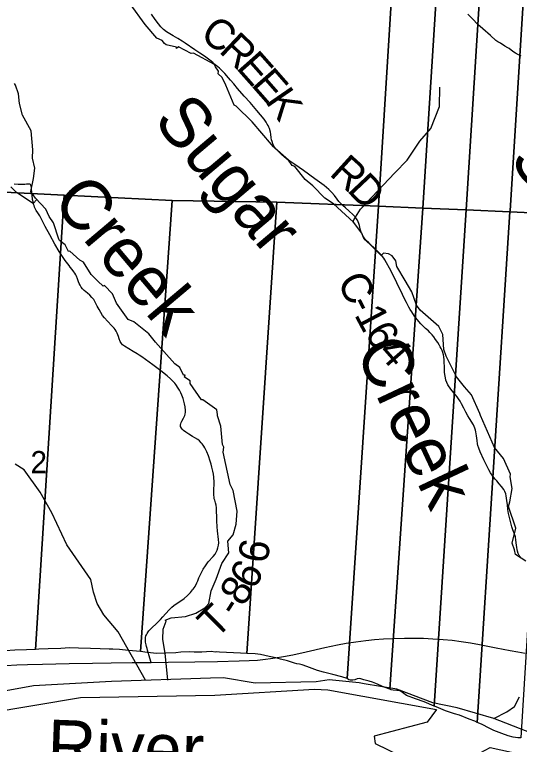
# Model space of a CAD drawing. Extents: x 0 to 34, y 0 to 22.
# Drawn here: x 28.533 to 29.485, y 15.294 to 16.671 of the extents above; entities that cross this region are included whole.
import ezdxf

# ---------------------------------------------------------------- set-up
doc = ezdxf.new("R2010")
doc.units = 0
for name, color, linetype in [('GM_X_County_Road', 7, 'Continuous'), ('GM_X_County_Road_Text', 7, 'Continuous'), ('GM_X_County_Text', 7, 'Continuous'), ('GM_X_Major_River', 7, 'Continuous'), ('GM_X_Major_River_Text', 7, 'Continuous'), ('GM_X_Minor_River', 7, 'Continuous'), ('GM_X_Minor_River_Text', 7, 'Continuous'), ('GM_X_Section', 7, 'Continuous'), ('GM_X_Section_Text', 7, 'Continuous'), ('GM_X_State_Route', 7, 'Continuous'), ('GM_X_Township_Road', 7, 'Continuous'), ('GM_X_Township_Road_Text', 7, 'Continuous'), ('SH_Cut_Line', 7, 'Continuous')]:
    doc.layers.add(name, color=color, linetype=linetype)

msp = doc.modelspace()

# ---------------------------------------------------------------- linework, layer by layer
at = {"layer": 'GM_X_County_Road'}
for points in [[(29.4879, 15.6455), (29.4848, 15.6503), (29.4829, 15.6542), (29.4816, 15.6581), (29.4808, 15.6614), (29.4803, 15.6655), (29.4799, 15.6698), (29.4788, 15.679), (29.4778, 15.6852), (29.4755, 15.6921), (29.473, 15.6984), (29.4711, 15.7043), (29.4678, 15.7168), (29.465, 15.7294), (29.4637, 15.737), (29.4625, 15.7459), (29.4616, 15.7542), (29.4605, 15.7627), (29.4596, 15.7668), (29.4577, 15.7711), (29.4556, 15.7746), (29.4516, 15.7801), (29.4468, 15.7857), (29.4424, 15.7908), (29.4393, 15.7944), (29.4349, 15.8), (29.431, 15.806), (29.4277, 15.8118), (29.4183, 15.8305), (29.411, 15.8461), (29.4085, 15.8527), (29.4069, 15.8576), (29.4064, 15.8611), (29.4053, 15.8675), (29.4042, 15.876), (29.4038, 15.88), (29.4032, 15.8837), (29.4025, 15.8866), (29.4011, 15.8907), (29.3984, 15.8968), (29.3911, 15.9086), (29.3878, 15.9139), (29.3844, 15.9205), (29.3803, 15.9284), (29.3763, 15.9361), (29.3732, 15.9415), (29.3703, 15.9458), (29.3675, 15.9499), (29.3618, 15.9572), (29.3559, 15.9643), (29.3503, 15.9724), (29.3481, 15.9768), (29.3463, 15.9813), (29.3455, 15.9852), (29.3449, 15.9884), (29.344, 15.9956), (29.3436, 16.0053), (29.3432, 16.0157), (29.343, 16.0196), (29.3425, 16.0248), (29.342, 16.0287), (29.3407, 16.0334), (29.3392, 16.0371), (29.3374, 16.0407), (29.3358, 16.0441), (29.3338, 16.0479), (29.3311, 16.0521), (29.3271, 16.0579), (29.3235, 16.0628), (29.3204, 16.0665), (29.3164, 16.0708), (29.3135, 16.074), (29.3083, 16.0789), (29.3045, 16.0825), (29.2995, 16.0874), (29.2924, 16.0953), (29.2873, 16.102), (29.2823, 16.1098), (29.2794, 16.1146), (29.2769, 16.1188), (29.2723, 16.1276), (29.2687, 16.1344), (29.2648, 16.1429), (29.2538, 16.1648), (29.2445, 16.1841), (29.2402, 16.1923), (29.2346, 16.2026), (29.2316, 16.2082), (29.2293, 16.2115), (29.2249, 16.217), (29.215, 16.2269), (29.2009, 16.2402), (29.1961, 16.2449), (29.1923, 16.2497), (29.1898, 16.2537), (29.1883, 16.2569), (29.1869, 16.2603), (29.1856, 16.2643), (29.1844, 16.2696), (29.1835, 16.2732), (29.1821, 16.2771), (29.1811, 16.2802), (29.1797, 16.2828), (29.1773, 16.2865), (29.1752, 16.2891), (29.1717, 16.2931), (29.1636, 16.3005), (29.157, 16.3064), (29.1521, 16.311), (29.1481, 16.3147), (29.1445, 16.3186), (29.1414, 16.3225), (29.1362, 16.3295), (29.1312, 16.3354), (29.1255, 16.341), (29.1165, 16.3486), (29.0991, 16.3611), (29.0775, 16.377), (29.0695, 16.3828), (29.0617, 16.3882), (29.0519, 16.3945), (29.046, 16.3991), (29.0363, 16.4071), (29.0293, 16.4137), (29.0252, 16.4181), (29.0219, 16.4228), (29.0198, 16.4269), (29.0184, 16.4314), (29.0176, 16.4348), (29.017, 16.4386), (29.0162, 16.4455), (29.0154, 16.4492), (29.0136, 16.4558), (29.0124, 16.4589), (29.0111, 16.4619), (29.0095, 16.4646), (29.0074, 16.468), (29.0033, 16.474), (28.9899, 16.4901), (28.9771, 16.5049), (28.9659, 16.5173), (28.9533, 16.5316), (28.9462, 16.5403), (28.9401, 16.5474), (28.9365, 16.5516), (28.9292, 16.5599), (28.9228, 16.5661), (28.9191, 16.5697), (28.913, 16.5753), (28.9069, 16.5805), (28.901, 16.5854), (28.8907, 16.5924), (28.8822, 16.5982), (28.8728, 16.6045), (28.8547, 16.6174), (28.8491, 16.6212), (28.8405, 16.6263), (28.832, 16.6312), (28.8253, 16.6351), (28.8193, 16.6388), (28.8137, 16.6429), (28.8085, 16.6479), (28.804, 16.6534), (28.7977, 16.6619), (28.791, 16.6722)], [(29.4888, 16.5932), (29.4837, 16.5953), (29.4782, 16.5983), (29.4745, 16.6005), (29.4699, 16.6042), (29.466, 16.607), (29.4636, 16.6084), (29.4577, 16.6117), (29.4493, 16.617), (29.4448, 16.6197), (29.4408, 16.6225), (29.4309, 16.6314), (29.416, 16.6442), (29.4111, 16.6488), (29.4071, 16.6525), (29.3968, 16.6634), (29.3881, 16.6719)]]:
    msp.add_lwpolyline(points, dxfattribs=at)
at = {"layer": 'GM_X_County_Text'}
msp.add_lwpolyline([(28.4427, 17.7695), (28.4159, 17.3358), (28.3944, 17.0528), (28.3527, 16.4269), (28.2867, 15.4004), (28.2799, 15.2948), (28.3301, 15.293), (28.3692, 15.2637), (28.4182, 15.3245), (28.4801, 15.3522), (28.6571, 15.3822), (28.9104, 15.3867), (29.0987, 15.3975), (29.1238, 15.3963), (29.3286, 15.3596), (29.3112, 15.3354), (29.211, 15.3094), (29.213, 15.295), (29.3097, 15.2479), (29.423, 15.2518), (29.4264, 15.2648), (29.4018, 15.2725), (29.4304, 15.2876), (29.5713, 15.2568)], dxfattribs=at)
at = {"layer": 'GM_X_Major_River'}
for points in [[(29.1018, 15.4118), (28.9867, 15.4094), (28.927, 15.4195), (28.9024, 15.4184), (28.7152, 15.4124), (28.568, 15.4039), (28.5098, 15.3936), (28.3722, 15.373)], [(29.5453, 15.3005), (29.4369, 15.3424), (29.3679, 15.3624), (29.3216, 15.3722), (29.2538, 15.3976), (29.1924, 15.4081), (29.1829, 15.4096), (29.1264, 15.4156), (29.1018, 15.4118)]]:
    msp.add_lwpolyline(points, dxfattribs=at)
at = {"layer": 'GM_X_Minor_River'}
for points in [[(29.4972, 15.6396), (29.4779, 15.6521), (29.476, 15.6605), (29.4719, 15.6734), (29.4783, 15.7019), (29.4646, 15.7429), (29.4669, 15.7516), (29.4714, 15.7764), (29.4676, 15.7988), (29.4687, 15.8037), (29.4555, 15.833), (29.4381, 15.8538), (29.4116, 15.9142), (29.4108, 15.9184), (29.3949, 15.9537), (29.3816, 15.9685), (29.3665, 15.9874), (29.3468, 16.0261), (29.3426, 16.0387), (29.3407, 16.0672), (29.3335, 16.0824), (29.298, 16.1131), (29.2912, 16.1225), (29.2824, 16.148), (29.2696, 16.1689), (29.254, 16.1954), (29.2521, 16.2064), (29.2449, 16.2159), (29.2385, 16.2193), (29.2287, 16.2205), (29.2242, 16.2166), (29.2033, 16.2375), (29.1924, 16.2474), (29.1878, 16.2584), (29.1723, 16.2796), (29.1345, 16.3137), (29.1178, 16.3243), (29.0955, 16.3478), (29.0811, 16.3596), (29.0615, 16.3843), (29.0565, 16.3861), (29.0494, 16.3964), (29.0187, 16.4237), (29.0172, 16.4256), (28.9812, 16.4688), (28.9506, 16.4984), (28.9468, 16.4999), (28.9313, 16.5379), (28.9245, 16.5523), (28.9169, 16.5595), (28.9173, 16.5644), (28.912, 16.5724), (28.9097, 16.577), (28.87, 16.5985), (28.8658, 16.5974), (28.842, 16.6103), (28.8382, 16.6072), (28.8382, 16.6095), (28.8186, 16.614), (28.8155, 16.6163), (28.811, 16.622), (28.8008, 16.6269), (28.7788, 16.6523), (28.7504, 16.6914)], [(28.8218, 15.4148), (28.8169, 15.4659), (28.8124, 15.4917), (28.8127, 15.5111), (28.8184, 15.5263), (28.8169, 15.5282), (28.8282, 15.5324), (28.8551, 15.5352), (28.8747, 15.5413), (28.8913, 15.5512), (28.8932, 15.5535), (28.8989, 15.5592), (28.9034, 15.5835), (28.9132, 15.6052), (28.9238, 15.6349), (28.937, 15.6551), (28.9351, 15.6771), (28.9453, 15.6889), (28.9509, 15.709), (28.9528, 15.7338), (28.9452, 15.7725), (28.9391, 15.7843), (28.9262, 15.8454), (28.9277, 15.8549), (28.9247, 15.8599), (28.922, 15.8941), (28.9156, 15.9138), (28.9156, 15.9165), (28.9141, 15.9248), (28.888, 15.9442), (28.8853, 15.9441), (28.8641, 15.9749), (28.8641, 15.9798), (28.8535, 15.987), (28.8543, 15.9908), (28.8513, 15.9904), (28.8444, 16.0052), (28.835, 16.0121), (28.7983, 16.0526), (28.7858, 16.0686), (28.7608, 16.0887), (28.7574, 16.0913), (28.7472, 16.0958), (28.7249, 16.1266), (28.7173, 16.144), (28.7025, 16.1596), (28.6995, 16.1584), (28.6897, 16.1679), (28.6772, 16.1804), (28.6624, 16.204), (28.6556, 16.2074), (28.6367, 16.2244), (28.6341, 16.224), (28.628, 16.2366), (28.6174, 16.2445), (28.6159, 16.2472), (28.606, 16.2779), (28.5981, 16.2901), (28.5913, 16.3041), (28.5723, 16.3246), (28.5633, 16.3375), (28.5682, 16.3618), (28.5708, 16.3812), (28.5666, 16.3998), (28.567, 16.4158), (28.5639, 16.4519), (28.5476, 16.4815), (28.5416, 16.5032), (28.54, 16.5218), (28.534, 16.5377), (28.5325, 16.5408)], [(29.1716, 16.2796), (29.1729, 16.2836), (29.1856, 16.3037), (29.2504, 16.3722), (29.2734, 16.3962), (29.2976, 16.4319), (29.3179, 16.4559), (29.3343, 16.4979), (29.3354, 16.5339)], [(28.5745, 16.3223), (28.5678, 16.3147), (28.536, 16.3355), (28.5255, 16.3458)], [(28.7794, 15.4148), (28.7281, 15.5058), (28.7011, 15.5384), (28.6882, 15.5593), (28.6817, 15.5806), (28.6763, 15.6049), (28.631, 15.6705), (28.6028, 15.7309), (28.5807, 15.7696), (28.5507, 15.8117), (28.5339, 15.8227)], [(29.4369, 15.3424), (29.4616, 15.3553), (29.4759, 15.3652), (29.4857, 15.3831)]]:
    msp.add_lwpolyline(points, dxfattribs=at)
at = {"layer": 'GM_X_Section'}
for points in [[(28.2266, 17.4004), (29.2849, 17.3606), (29.2195, 16.3096), (29.0277, 16.3171), (28.8298, 16.3203), (28.6263, 16.3303), (28.4372, 16.34), (28.2749, 16.348), (28.1612, 16.354), (28.2124, 17.1731)], [(29.3695, 17.3565), (29.303, 16.306), (29.2195, 16.3096), (29.2849, 17.3606)], [(29.4508, 17.3523), (29.3847, 16.3023), (29.303, 16.306), (29.3695, 17.3565)], [(29.5335, 17.3481), (29.4676, 16.3015), (29.4674, 16.2986), (29.3847, 16.3023), (29.4508, 17.3523)], [(29.6192, 17.3436), (29.5493, 16.2992), (29.5491, 16.295), (29.4674, 16.2986), (29.4676, 16.3015), (29.5335, 17.3481)], [(28.4372, 16.34), (28.6263, 16.3303), (28.572, 15.4729), (28.5552, 15.472), (28.5329, 15.4712), (28.5147, 15.4704), (28.5048, 15.4689), (28.4954, 15.4662), (28.4813, 15.4643), (28.4741, 15.4632), (28.4635, 15.4627), (28.437, 15.4612), (28.4162, 15.4596), (28.3889, 15.4573), (28.3846, 15.4569)], [(28.6263, 16.3303), (28.8298, 16.3203), (28.77, 15.4686), (28.7473, 15.4709), (28.7306, 15.4724), (28.7181, 15.4735), (28.7113, 15.4735), (28.6939, 15.4742), (28.6761, 15.4746), (28.6533, 15.4749), (28.6363, 15.4756), (28.6196, 15.4748), (28.5957, 15.474), (28.5783, 15.4732), (28.572, 15.4729)], [(28.8298, 16.3203), (29.0277, 16.3171), (28.9709, 15.4654), (28.9586, 15.4656), (28.9192, 15.4678), (28.9143, 15.4685), (28.9118, 15.4679), (28.9038, 15.4686), (28.886, 15.4678), (28.8712, 15.4678), (28.8633, 15.4681), (28.8466, 15.4674), (28.8367, 15.4666), (28.8178, 15.4658), (28.8011, 15.4654), (28.7829, 15.4672), (28.77, 15.4686)], [(29.0277, 16.3171), (29.2195, 16.3096), (29.16, 15.4178), (29.1501, 15.4208), (29.1331, 15.4253), (29.1156, 15.4302), (29.1043, 15.4332), (29.0838, 15.4407), (29.0754, 15.4437), (29.0701, 15.4452), (29.0652, 15.4456), (29.061, 15.447), (29.0474, 15.4512), (29.0341, 15.4545), (29.0254, 15.4568), (29.0128, 15.4594), (28.9969, 15.4631), (28.9867, 15.4642), (28.9709, 15.4654)], [(29.303, 16.306), (29.2407, 15.3975), (29.2302, 15.4018), (29.2142, 15.4082), (29.2078, 15.4108), (29.2017, 15.4131), (29.1918, 15.4157), (29.1839, 15.4179), (29.1793, 15.4175), (29.1744, 15.4156), (29.1706, 15.4145), (29.1661, 15.4148), (29.1634, 15.4156), (29.16, 15.4178), (29.2195, 16.3096)], [(29.3847, 16.3023), (29.3246, 15.3658), (29.3057, 15.3736), (29.2893, 15.3796), (29.2723, 15.386), (29.267, 15.3894), (29.2624, 15.3932), (29.2582, 15.3951), (29.2537, 15.3954), (29.2472, 15.3958), (29.2431, 15.3965), (29.2407, 15.3975), (29.303, 16.306)], [(29.4674, 16.2986), (29.4057, 15.3352), (29.4013, 15.3372), (29.3906, 15.3414), (29.3721, 15.3485), (29.3629, 15.3515), (29.3459, 15.3571), (29.3284, 15.3643), (29.3246, 15.3658), (29.3847, 16.3023)], [(29.5491, 16.295), (29.4878, 15.3057), (29.4821, 15.3061), (29.4737, 15.3072), (29.4643, 15.3098), (29.4521, 15.3139), (29.4369, 15.3199), (29.4297, 15.3233), (29.4138, 15.3316), (29.4057, 15.3352), (29.4674, 16.2986)]]:
    msp.add_lwpolyline(points, close=True, dxfattribs=at)
at = {"layer": 'GM_X_State_Route'}
for points in [[(28.7905, 15.4484), (28.8221, 15.4488), (28.8729, 15.4496), (28.9156, 15.4502), (28.9566, 15.451), (28.9751, 15.4517), (28.9912, 15.4527), (29.006, 15.4542), (29.0153, 15.4554), (29.0244, 15.4567), (29.0403, 15.4593), (29.0579, 15.4628), (29.0827, 15.4683), (29.1178, 15.4765), (29.1422, 15.4816), (29.1586, 15.4846), (29.1765, 15.4874), (29.1956, 15.4898), (29.212, 15.4915), (29.2285, 15.4928), (29.2459, 15.4937), (29.2683, 15.4943), (29.2851, 15.4943), (29.3043, 15.4939), (29.3217, 15.4931), (29.3412, 15.4916), (29.3584, 15.49), (29.3753, 15.4879), (29.3927, 15.4852), (29.41, 15.482), (29.4415, 15.4758), (29.4677, 15.4707), (29.4825, 15.4681), (29.4963, 15.4658)], [(28.287, 15.3999), (28.3027, 15.4045), (28.3291, 15.4116), (28.3531, 15.4174), (28.376, 15.4225), (28.397, 15.4267), (28.4166, 15.4303), (28.4366, 15.4335), (28.4573, 15.4362), (28.4781, 15.4387), (28.4976, 15.4406), (28.5162, 15.4422), (28.537, 15.4436), (28.557, 15.4446), (28.5853, 15.4453), (28.6357, 15.4462), (28.6794, 15.4468), (28.7148, 15.4473), (28.7545, 15.4479), (28.7905, 15.4484)]]:
    msp.add_lwpolyline(points, dxfattribs=at)
at = {"layer": 'GM_X_Township_Road'}
for points in [[(28.8686, 15.5852), (28.8698, 15.5866), (28.8733, 15.5918), (28.8768, 15.5986), (28.8785, 15.6026), (28.8805, 15.6081), (28.8823, 15.612), (28.8851, 15.6182), (28.8886, 15.6246), (28.8927, 15.6308), (28.8979, 15.6383), (28.9074, 15.6484), (28.9109, 15.6528), (28.9131, 15.6565), (28.9147, 15.66), (28.9164, 15.6648), (28.9173, 15.6695), (28.9178, 15.6743), (28.9176, 15.6802), (28.9158, 15.6966), (28.9149, 15.7043), (28.9147, 15.7079), (28.9144, 15.7116), (28.9143, 15.7167), (28.9137, 15.74), (28.913, 15.7453), (28.912, 15.7495), (28.9103, 15.7543), (28.9095, 15.7572), (28.9091, 15.7598), (28.9087, 15.7646), (28.9084, 15.7712), (28.9089, 15.7884), (28.9085, 15.7979), (28.9078, 15.8036), (28.9069, 15.8091), (28.9048, 15.8169), (28.9034, 15.8222), (28.9015, 15.828), (28.8982, 15.8381), (28.8951, 15.8461), (28.8915, 15.8531), (28.8896, 15.8564), (28.8882, 15.8586), (28.8866, 15.8608), (28.8849, 15.8627), (28.8815, 15.8664), (28.8781, 15.8688), (28.873, 15.8721), (28.8684, 15.8749), (28.8612, 15.8794), (28.8559, 15.8827), (28.8511, 15.8862), (28.8488, 15.8883), (28.8473, 15.8904), (28.8459, 15.8933), (28.8455, 15.8953), (28.8456, 15.8972), (28.8462, 15.8989), (28.8469, 15.9009), (28.8484, 15.9035), (28.8514, 15.9091), (28.8537, 15.9141), (28.8546, 15.9172), (28.855, 15.9206), (28.8549, 15.9241), (28.8542, 15.9305), (28.8531, 15.9365), (28.852, 15.9415), (28.8506, 15.9462), (28.8484, 15.9525), (28.8463, 15.9572), (28.8439, 15.962), (28.8415, 15.9659), (28.8367, 15.9727), (28.8348, 15.9752), (28.8321, 15.9788), (28.827, 15.9834), (28.8202, 15.9892), (28.8085, 15.9986), (28.7934, 16.0101), (28.7799, 16.0199), (28.7727, 16.0248), (28.7675, 16.0282), (28.7639, 16.0305), (28.7566, 16.0351), (28.7399, 16.0451), (28.7364, 16.0477), (28.7342, 16.05), (28.7328, 16.052), (28.7316, 16.0542), (28.7299, 16.0593), (28.7287, 16.0637), (28.7264, 16.0695), (28.7243, 16.0736), (28.7225, 16.0766), (28.7202, 16.0795), (28.7163, 16.0837), (28.7081, 16.0923), (28.7025, 16.0987), (28.6986, 16.1034), (28.6951, 16.1086), (28.6919, 16.1142), (28.6882, 16.1207), (28.6848, 16.1286), (28.6818, 16.1334), (28.6785, 16.1374), (28.6744, 16.1416), (28.67, 16.1455), (28.6641, 16.1502), (28.6609, 16.1536), (28.6582, 16.1569), (28.656, 16.1604), (28.6545, 16.1633), (28.6532, 16.1667), (28.651, 16.1725), (28.6493, 16.1771), (28.6479, 16.18), (28.6462, 16.183), (28.6445, 16.1858), (28.6411, 16.1902), (28.6377, 16.1946), (28.6354, 16.1975), (28.6282, 16.2068), (28.6252, 16.2109), (28.6215, 16.2164), (28.6168, 16.2241), (28.6085, 16.2379), (28.599, 16.2551), (28.5904, 16.2714), (28.58, 16.2912), (28.5767, 16.2967), (28.5735, 16.3015), (28.5704, 16.3074), (28.5692, 16.3107), (28.5683, 16.3134), (28.5673, 16.3179), (28.5665, 16.3224), (28.5657, 16.3305), (28.5653, 16.3362), (28.5646, 16.3422), (28.5644, 16.3448), (28.5639, 16.3475), (28.5633, 16.349), (28.5624, 16.3501), (28.5613, 16.3508), (28.5598, 16.3512), (28.5586, 16.3513), (28.5572, 16.3512), (28.5553, 16.351), (28.5516, 16.3506), (28.5492, 16.3503), (28.5449, 16.3502), (28.5424, 16.3502), (28.5393, 16.3503), (28.5319, 16.3511)], [(28.8173, 15.5398), (28.8179, 15.5405), (28.8244, 15.5477), (28.8296, 15.5527), (28.833, 15.5557), (28.8376, 15.5587), (28.8447, 15.5636), (28.8523, 15.5692), (28.8588, 15.5749), (28.8645, 15.5803), (28.8686, 15.5852)], [(28.7905, 15.4484), (28.7881, 15.4562), (28.7837, 15.4712), (28.7826, 15.4747), (28.7817, 15.4783), (28.7809, 15.4813), (28.7803, 15.4839), (28.7798, 15.4867), (28.7796, 15.4898), (28.7796, 15.4923), (28.7799, 15.4955), (28.7805, 15.4983), (28.7814, 15.5005), (28.7827, 15.503), (28.7847, 15.5061), (28.7861, 15.5078), (28.7883, 15.5103), (28.7908, 15.5129), (28.8012, 15.5227), (28.8078, 15.5292), (28.8122, 15.5341), (28.8173, 15.5398)]]:
    msp.add_lwpolyline(points, dxfattribs=at)
at = {"layer": 'SH_Cut_Line'}
msp.add_lwpolyline([(28.3692, 15.2637), (28.4182, 15.3245), (28.4801, 15.3522), (28.6571, 15.3822), (28.9104, 15.3867), (29.0987, 15.3975), (29.1238, 15.3963), (29.3286, 15.3596), (29.3112, 15.3354), (29.211, 15.3094), (29.213, 15.295), (29.3097, 15.2479)], dxfattribs=at)

# ---------------------------------------------------------------- texts
at = {"layer": 'GM_X_County_Road_Text'}
for s, rotation, p in [('C', 324.0036, (28.88, 16.6274)), ('R', 316.4353, (28.9163, 16.6012)), ('E', 311.5826, (28.9492, 16.57)), ('E', 311.267, (28.9773, 16.5382)), ('K', 304.6035, (29.0043, 16.5077)), ('R', 317.7996, (29.1247, 16.3693)), ('D', 313.3796, (29.1585, 16.3388)), ('C', 297.5557, (29.1402, 16.1671)), ('-', 297.6185, (29.1619, 16.1257)), ('1', 297.852, (29.1728, 16.1048)), ('6', 302.5796, (29.1917, 16.0694)), ('4', 311.2111, (29.2162, 16.0324))]:
    msp.add_text(s, height=0.0568, rotation=rotation, dxfattribs=at).set_placement(p)
at = {"layer": 'GM_X_Major_River_Text'}
msp.add_text('River', height=0.0947, rotation=357.9954, dxfattribs=at).set_placement((28.5931, 15.246))
at = {"layer": 'GM_X_Minor_River_Text'}
for s, rotation, p in [('Sugar', 310.1349, (28.7924, 16.4699)), ('Stillhouse', 310.1347, (29.4639, 16.3951)), ('Creek', 310.135, (28.6007, 16.318)), ('Creek', 295.1343, (29.1747, 16.0372))]:
    msp.add_text(s, height=0.09469, rotation=rotation, dxfattribs=at).set_placement(p)
at = {"layer": 'GM_X_Section_Text'}
msp.add_text('2', height=0.0419, rotation=0, dxfattribs=at).set_placement((28.5626, 15.8054))
at = {"layer": 'GM_X_Township_Road_Text'}
for s, rotation, p in [('6', 79.4082, (29.0087, 15.633)), ('6', 59.6752, (28.9836, 15.5829)), ('8', 58.1295, (28.9642, 15.5517)), ('T', 44.6773, (28.9124, 15.4908)), ('-', 57.3982, (28.9512, 15.5314))]:
    msp.add_text(s, height=0.0568, rotation=rotation, dxfattribs=at).set_placement(p)

doc.saveas('drawing.dxf')
